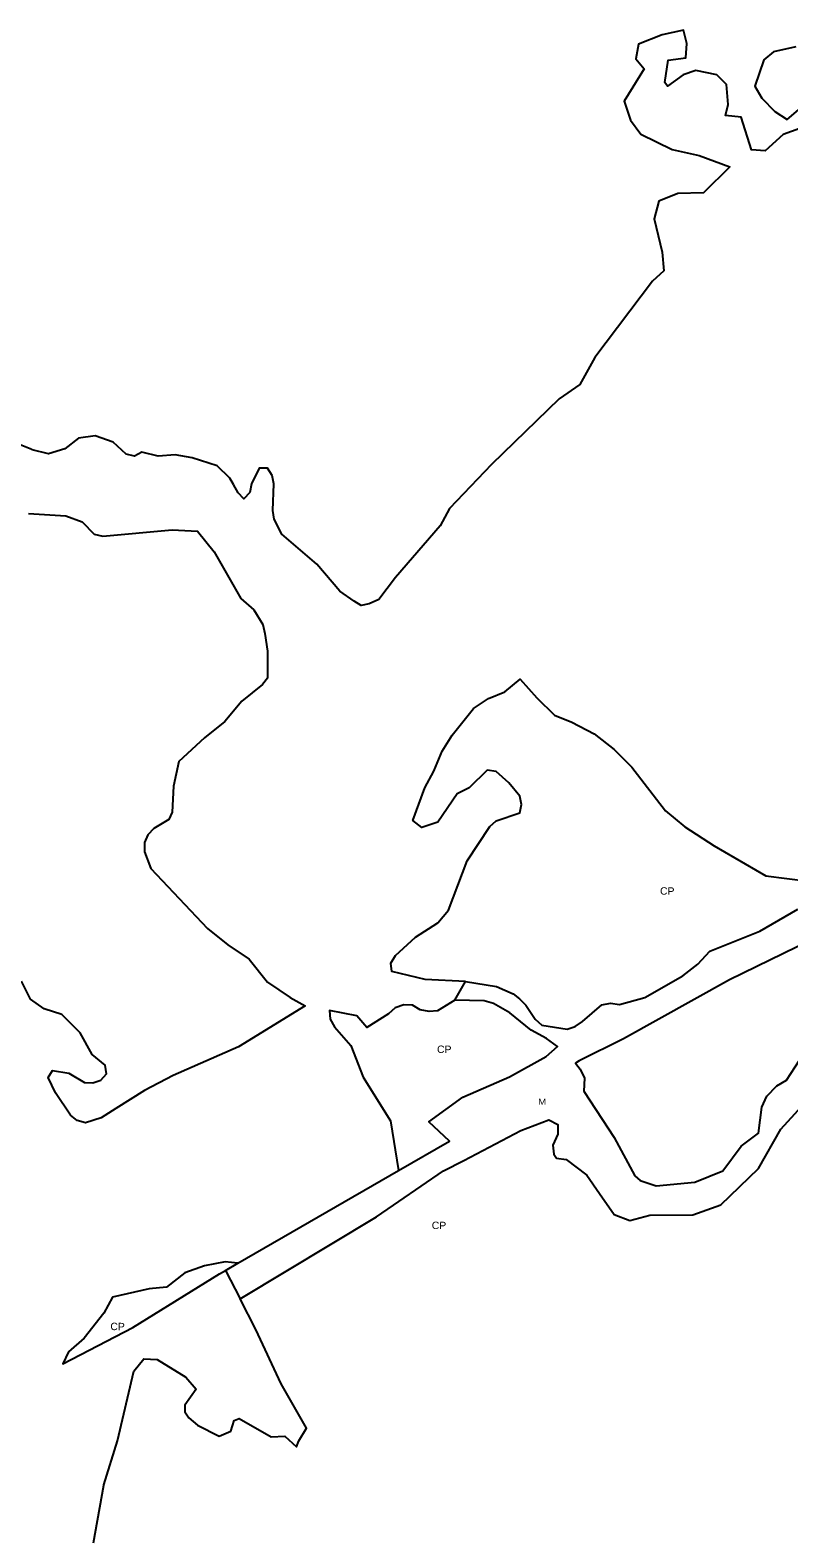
# Model space of a CAD drawing. Extents: x 713589 to 726391, y 7177764 to 7191819.
# Drawn here: x 724678 to 725333, y 7183880 to 7185181 of the extents above; entities that cross this region are included whole.
import ezdxf
from ezdxf.enums import TextEntityAlignment as Align

# ---------------------------------------------------------------- set-up
doc = ezdxf.new("R2010")
doc.units = 0
doc.header["$LTSCALE"] = 2.6
doc.layers.add('63', color=7, linetype='Continuous', lineweight=25)

msp = doc.modelspace()

# ---------------------------------------------------------------- linework, layer by layer
at = {"layer": '63'}
for p, q in [((725044.39, 7184343.99), (725053.6, 7184359.94)), ((724846.12, 7184110.71), (724858.82, 7184086.07))]:
    msp.add_line(p, q, dxfattribs=at)
for points in [[(725352.44, 7185100.02), (725327.87, 7185091.19), (725312.15, 7185077.11), (725300.36, 7185078.09), (725291.52, 7185106.26), (725278.1, 7185107.57), (725280.39, 7185117.07), (725278.76, 7185134.43), (725270.57, 7185142.61), (725252.23, 7185146.55), (725241.43, 7185142.62), (725228, 7185132.8), (725225.71, 7185136.07), (725228.33, 7185155.4), (725243.72, 7185157.36), (725244.71, 7185169.8), (725241.76, 7185181.26), (725223.42, 7185177.34), (725202.79, 7185169.16), (725200.49, 7185156.38), (725207.7, 7185147.87), (725190.33, 7185120.03), (725195.9, 7185103.66), (725204.74, 7185091.54), (725231.92, 7185078.11), (725255.17, 7185073.19), (725281.69, 7185063.36), (725259.09, 7185040.77), (725236.82, 7185040.12), (725220.44, 7185033.57), (725216.51, 7185018.51), (725223.38, 7184989.69), (725224.69, 7184973.64), (725214.86, 7184964.47), (725165.07, 7184898.66), (725152.29, 7184875.41), (725134.28, 7184862.97), (725075.97, 7184806.32), (725039.66, 7184768.37), (725031.47, 7184753.3), (724993.14, 7184708.77), (724978.73, 7184689.78), (724978.74, 7184689.78), (724970.17, 7184686.16), (724963.29, 7184684.52), (724957.4, 7184688.45), (724944.95, 7184696.97), (724924.98, 7184720.23), (724894.86, 7184746.11), (724888.31, 7184759.21), (724887, 7184766.74), (724887.99, 7184789.66), (724886.68, 7184796.87)], [(725338.7, 7185166.83), (725319.37, 7185162.58), (725311.18, 7185155.7), (725303.32, 7185132.78), (725309.21, 7185122.63), (725320.67, 7185111.16), (725331.15, 7185104.28), (725340.98, 7185112.47)], [(724886.68, 7184796.87), (724882.43, 7184803.09), (724875.22, 7184803.09), (724868.67, 7184789.67), (724867.36, 7184782.14), (724862.12, 7184776.57), (724857.2, 7184781.81), (724853.03, 7184789.21), (724850, 7184794.58), (724839.2, 7184805.07), (724817.58, 7184811.95), (724802.85, 7184814.57), (724788.11, 7184813.59), (724774.03, 7184816.87), (724767.81, 7184813.6), (724760.6, 7184815.23), (724749.14, 7184825.72), (724733.75, 7184830.96), (724719.34, 7184829), (724707.55, 7184819.83), (724693.47, 7184815.58), (724679.48, 7184819.08), (724679.06, 7184819.18), (724657.45, 7184828.03)], [(724676.1, 7184764.1), (724708.52, 7184762.13), (724722.6, 7184756.88), (724732.75, 7184746.08), (724740.28, 7184744.44), (724800.21, 7184749.99), (724822.16, 7184748.68), (724836.56, 7184730.99), (724859.48, 7184690.7), (724870.61, 7184680.88), (724878.47, 7184668.1), (724880.1, 7184660.57), (724882.39, 7184645.18), (724882.39, 7184621.92), (724878.13, 7184616.36), (724860.44, 7184601.95), (724845.7, 7184584.6), (724828.01, 7184570.52), (724806.07, 7184549.89), (724801.48, 7184528.61), (724800.16, 7184506.34), (724797.21, 7184499.79), (724784.44, 7184492.26), (724779.2, 7184486.69), (724776.25, 7184480.14), (724776.25, 7184471.96), (724781.81, 7184457.55), (724830.6, 7184405.79), (724848.28, 7184391.71)], [(725053.6, 7184359.94), (725018.57, 7184361.93), (724989.75, 7184368.82), (724989.09, 7184376.02), (724993.03, 7184382.57), (725010.39, 7184398.29), (725029.71, 7184410.73), (725038.88, 7184421.53), (725054.94, 7184464.1), (725074.59, 7184493.9), (725079.84, 7184498.81), (725100.47, 7184505.68), (725101.78, 7184512.89), (725100.47, 7184520.09), (725090.98, 7184531.56), (725079.84, 7184541.39), (725072.31, 7184542.37), (725056.59, 7184527.31), (725046.2, 7184522.16), (725029.73, 7184497.51), (725015.65, 7184492.93), (725008.12, 7184499.15), (725018.27, 7184527.32), (725026.14, 7184541.72), (725033.34, 7184558.75), (725041.86, 7184572.83), (725060.53, 7184595.75), (725073.31, 7184604.26), (725087.39, 7184610.16), (725100.68, 7184621.08), (725114.94, 7184604.93), (725130.33, 7184589.86), (725145.4, 7184583.97), (725164.71, 7184573.81), (725181.74, 7184560.38), (725197.13, 7184544.98), (725226.27, 7184507.32), (725242.97, 7184493.56), (725268.18, 7184477.18), (725312.71, 7184451.3), (725367.08, 7184444.41)], [(725053.6, 7184359.94), (725080.13, 7184355.7), (725094.54, 7184349.47), (725100.11, 7184345.21), (725105.67, 7184339.65), (725113.53, 7184327.53), (725119.42, 7184322.29), (725141.36, 7184319.01), (725148.24, 7184321.3), (725154.47, 7184325.55), (725171.17, 7184339.96), (725178.7, 7184341.27), (725186.56, 7184340.28), (725208.18, 7184346.17), (725241.26, 7184364.83), (725254.03, 7184374.98), (725264.52, 7184386.12), (725307.75, 7184403.46), (725340.5, 7184422.45)], [(725374.2, 7184406.71), (725281.28, 7184361.43), (725190.01, 7184310.56), (725151.6, 7184291.53), (725148.32, 7184289.48), (725152.53, 7184284.52), (725156.36, 7184276.5), (725155.72, 7184265.45), (725181.82, 7184225.37), (725199.54, 7184192.33), (725204.28, 7184188.23), (725218.01, 7184183.77), (725251.54, 7184186.87), (725275.55, 7184196.58), (725291.36, 7184218.05), (725306.47, 7184229.15), (725309.27, 7184251.51), (725313.66, 7184260.98), (725322.29, 7184269.86), (725330.56, 7184274.75), (725341.75, 7184292.12)], [(724848.28, 7184391.71), (724866.61, 7184379.26), (724882.48, 7184359.51), (724902.22, 7184346.26), (724915.15, 7184339.16), (724857.35, 7184303.7), (724801.01, 7184278.82), (724776.45, 7184266.06), (724751.6, 7184250.46), (724738.86, 7184242.4), (724725.44, 7184238.14), (724718.23, 7184240.11), (724712.34, 7184244.69), (724699.57, 7184264.02), (724693.02, 7184277.12), (724696.95, 7184283.34), (724711.04, 7184281.05), (724724.46, 7184272.86), (724731.67, 7184272.53), (724738.54, 7184274.82), (724743.46, 7184280.38), (724742.48, 7184287.92), (724731.02, 7184297.09), (724720.87, 7184315.76), (724704.82, 7184331.48), (724689.76, 7184336.4), (724677.97, 7184344.91), (724670.12, 7184360.31)], [(725044.39, 7184343.99), (725029.37, 7184334.69), (725022.16, 7184334.03), (725014.3, 7184335.67), (725007.75, 7184339.6), (725000.22, 7184339.93), (724992.69, 7184337.31), (724987.12, 7184332.07), (724968.23, 7184320.29), (724959.53, 7184330.53), (724936.09, 7184335.09), (724936.69, 7184327.5), (724940.29, 7184320.95), (724954.37, 7184304.9), (724965.17, 7184277.39), (724988.74, 7184239.72), (724995.67, 7184196.93)], [(724995.67, 7184196.93), (725039.75, 7184222.34), (725021.92, 7184239.06), (725051.29, 7184260.34), (725091.58, 7184277.69), (725123.02, 7184295.37), (725132.82, 7184304.01), (725123.43, 7184310.94), (725110.13, 7184318.17), (725091.85, 7184333.12), (725077.55, 7184341.05), (725069.58, 7184343.34), (725044.39, 7184343.99)], [(724858.82, 7184086.07), (724976.51, 7184156.93), (725034.59, 7184196.57), (725051.94, 7184205.65), (725101.34, 7184231.52), (725125.55, 7184240.58), (725133.11, 7184236.72), (725133.15, 7184228.35), (725129.02, 7184218.84), (725129.62, 7184211.04), (725132.15, 7184207.7), (725140.52, 7184206.36), (725158.17, 7184192.79), (725169.06, 7184177.15), (725181.78, 7184158.89), (725195.48, 7184153.66), (725212.75, 7184158.5), (725249.84, 7184158.7), (725274.06, 7184167.2), (725306.52, 7184198.62), (725325.86, 7184232.47), (725371.06, 7184282.09)], [(724846.12, 7184110.71), (724856.99, 7184116.98), (724995.67, 7184196.93)], [(724856.99, 7184116.98), (724846.05, 7184117.95), (724828.22, 7184114.65), (724811.05, 7184108.71), (724795.19, 7184096.16), (724780.33, 7184094.85), (724748.63, 7184087.59), (724741.36, 7184073.72), (724724.18, 7184052.26), (724710.64, 7184040.37), (724705.94, 7184029.97), (724766.15, 7184061.49), (724841.01, 7184107.76), (724846.12, 7184110.71)], [(724732.24, 7183875.45), (724741.19, 7183925.33), (724741.24, 7183925.63), (724752.95, 7183963.43), (724767.13, 7184023.75), (724775.72, 7184034.4), (724787.16, 7184033.9), (724812.06, 7184018.42), (724821.05, 7184008.15), (724811.08, 7183994.43), (724811.11, 7183988.57), (724814.49, 7183983.29), (724822.05, 7183977.19), (724840.79, 7183967.53), (724850.81, 7183972.05), (724853.83, 7183980.99), (724858, 7183982.97), (724885.7, 7183966.94), (724897.41, 7183967.56), (724907.63, 7183958.33), (724909.44, 7183963.52), (724916.11, 7183974.59), (724894.37, 7184012.78), (724872.36, 7184059.8), (724858.82, 7184086.07)]]:
    msp.add_lwpolyline(points, dxfattribs=at)

# ---------------------------------------------------------------- texts
for s, height, width, p in [('CP', 6.4, 1.05, (725227.61, 7184434.96)), ('CP', 6.4, 1.05, (725035.09, 7184298.34)), ('M', 5.2, 1.2, (725119.65, 7184253.67)), ('CP', 6.4, 1.05, (725030.53, 7184146.32)), ('CP', 6.4, 1.05, (724753.05, 7184059.07))]:
    msp.add_text(s, height=height, rotation=359.062, dxfattribs=dict(at, width=width)).set_placement(p, align=Align.CENTER)

doc.saveas('drawing.dxf')
